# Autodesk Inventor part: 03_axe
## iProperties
Created: 2002-11
Part Number: 03_axe
Material: Acier doux
Document SubType Name: Modélisation
Designer: poste-2
Control State: 0
Master: False
Checked Out: False
Shininess: 31.0
Length Units: 11269
Angle Units: 11279
Time Units: 11290
Mass Units: 11283
Length Display Precision: 3
Angle Display Precision: 2
Compacted: True
Density: 7.86
Volumn: 1.677510786885382
Area: 10.323396518310158
PropertySet Name: Model Information
Author: poste-2
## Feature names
1. Révolution1 [Revolution]
2. Extrusion1
3. Extrusion2
